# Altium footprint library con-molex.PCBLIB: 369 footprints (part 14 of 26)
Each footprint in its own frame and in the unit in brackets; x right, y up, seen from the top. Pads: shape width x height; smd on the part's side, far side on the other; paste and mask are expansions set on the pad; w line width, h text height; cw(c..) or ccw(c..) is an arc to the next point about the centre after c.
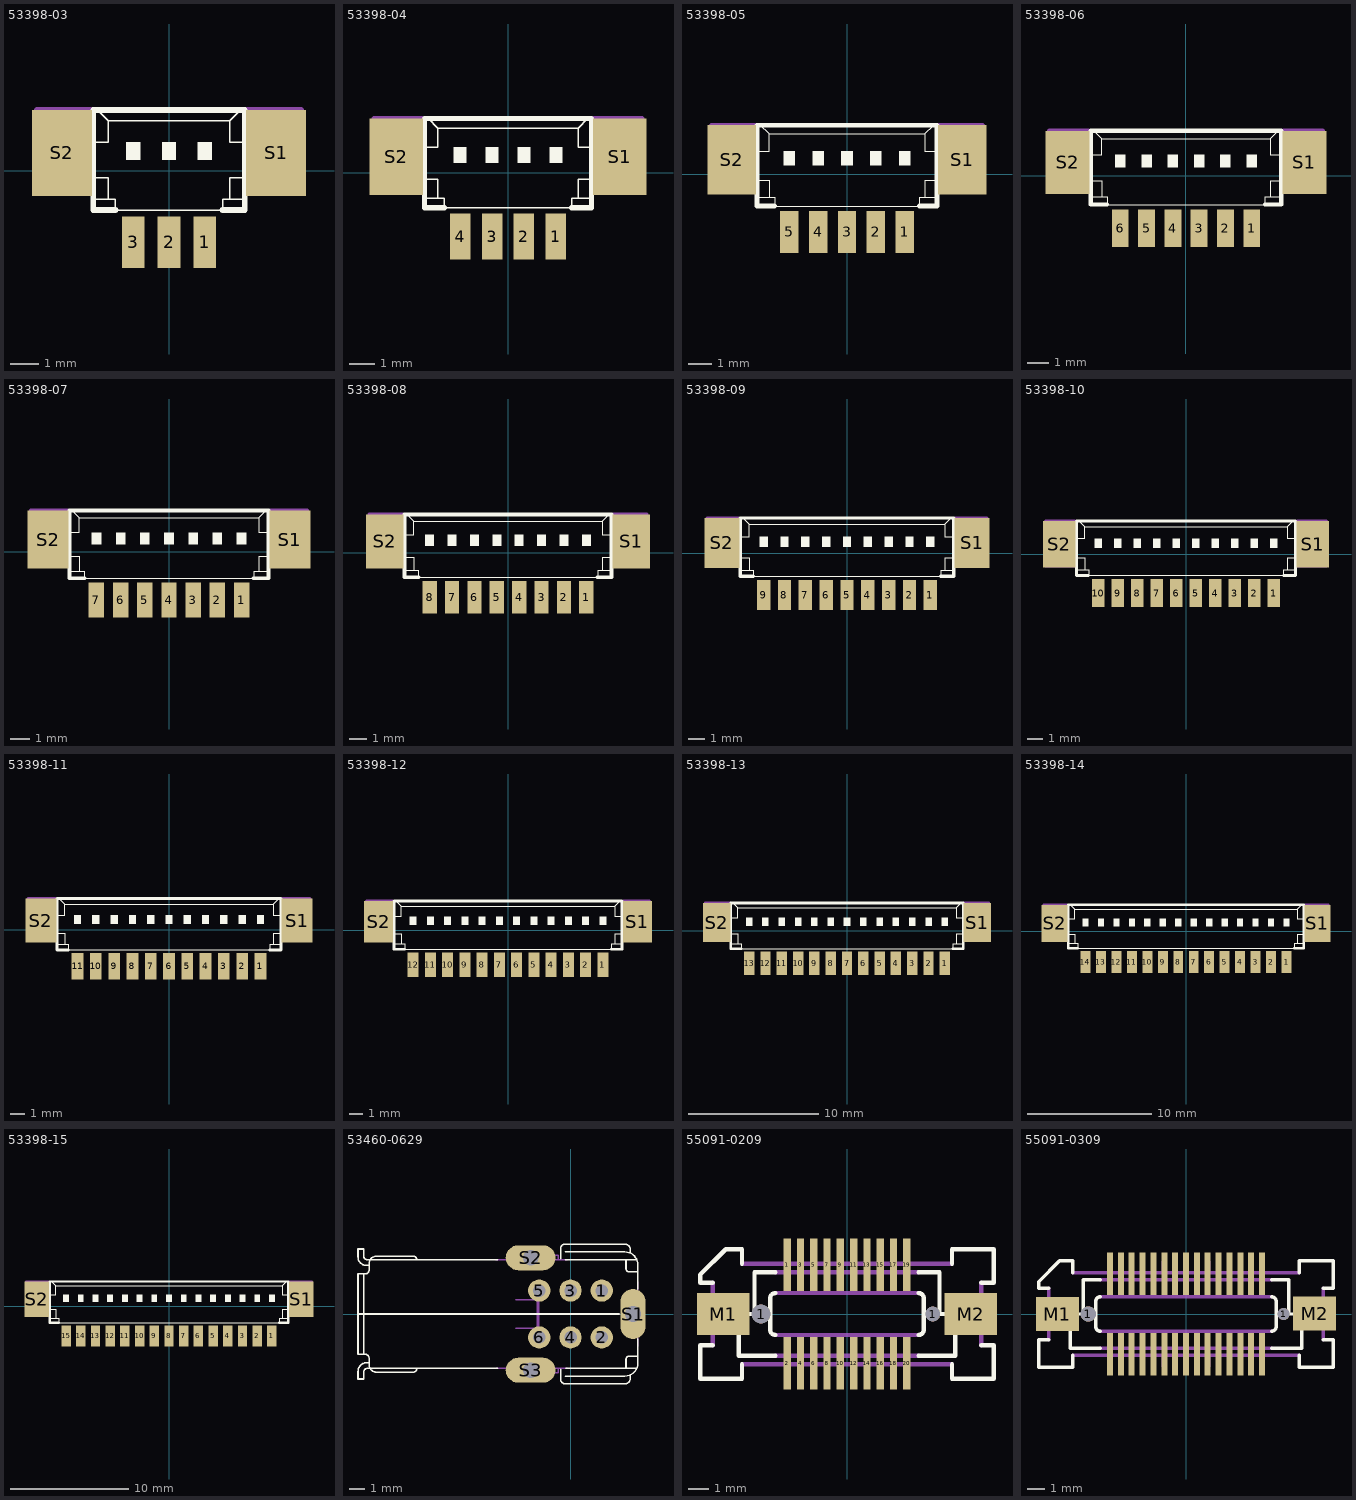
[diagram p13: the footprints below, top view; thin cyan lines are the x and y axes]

## 53398-03 [mil]
pads (5):
  rect 31.5x70.87 smd: 1(49.21,-98.43) 2(0,-98.43) 3(-49.21,-98.43)
  rect 82.68x118.11 smd: S1(147.64,24.61) S2(-147.64,24.61)
Top Overlay:
  rectangle: -59.06,14.76 -39.37,39.37
  rectangle: -9.84,14.76 9.84,39.37
  rectangle: 39.37,14.76 59.06,39.37
  lines w2: -103.35,-39.37 -83.66,-39.37 ; -103.35,-9.84 -83.66,-9.84 -83.66,-39.37 ; -103.35,39.37 -83.66,39.37 -83.66,68.9 ; -98.43,83.66 -83.66,68.9 ; 98.43,83.66 83.66,68.9 ; 103.35,-39.37 83.66,-39.37 ; 103.35,-9.84 83.66,-9.84 83.66,-39.37 ; 103.35,39.37 83.66,39.37 83.66,68.9 ; -83.66,-39.37 -73.82,-39.37 -73.82,-54.13 73.82,-54.13 73.82,-39.37 83.66,-39.37 ; -83.66,68.9 83.66,68.9
  lines w8: -73.82,-54.13 -104.33,-54.13 -104.33,83.66 -98.43,83.66 98.43,83.66 104.33,83.66 104.33,-54.13 73.82,-54.13
Mechanical 16:
  lines w8: -108.27,-29.53 -182.09,-29.53 -182.09,83.66 -108.27,83.66 ; 108.27,-29.53 182.09,-29.53 182.09,83.66 108.27,83.66
  text "1" at 123.03,-9.84 h117.8

## 53398-04 [mil]
pads (6):
  rect 31.5x70.87 smd: 1(73.82,-98.43) 2(24.61,-98.43) 3(-24.61,-98.43) 4(-73.82,-98.43)
  rect 82.68x118.11 smd: S1(172.24,24.61) S2(-172.24,24.61)
Top Overlay:
  rectangle: -83.66,14.76 -63.98,39.37
  rectangle: -34.45,14.76 -14.76,39.37
  rectangle: 14.76,14.76 34.45,39.37
  rectangle: 63.98,14.76 83.66,39.37
  lines w2: -127.95,-39.37 -108.27,-39.37 ; -127.95,-9.84 -108.27,-9.84 -108.27,-39.37 ; -127.95,39.37 -108.27,39.37 -108.27,68.9 ; -123.03,83.66 -108.27,68.9 ; 123.03,83.66 108.27,68.9 ; 127.95,-39.37 108.27,-39.37 ; 127.95,-9.84 108.27,-9.84 108.27,-39.37 ; 127.95,39.37 108.27,39.37 108.27,68.9 ; -108.27,-39.37 -98.43,-39.37 -98.43,-54.13 98.43,-54.13 98.43,-39.37 108.27,-39.37 ; -108.27,68.9 108.27,68.9
  lines w8: -98.43,-54.13 -128.94,-54.13 -128.94,83.66 -123.03,83.66 123.03,83.66 128.94,83.66 128.94,-54.13 98.43,-54.13
Mechanical 16:
  lines w8: -132.87,-29.53 -206.69,-29.53 -206.69,83.66 -132.87,83.66 ; 132.87,-29.53 206.69,-29.53 206.69,83.66 132.87,83.66
  text "1" at 147.64,-9.84 h117.8

## 53398-05 [mil]
pads (7):
  rect 31.5x70.87 smd: 1(98.43,-98.43) 2(49.21,-98.43) 3(0,-98.43) 4(-49.21,-98.43) 5(-98.43,-98.43)
  rect 82.68x118.11 smd: S1(196.85,24.61) S2(-196.85,24.61)
Top Overlay:
  rectangle: -108.27,14.76 -88.58,39.37
  rectangle: -59.06,14.76 -39.37,39.37
  rectangle: -9.84,14.76 9.84,39.37
  rectangle: 39.37,14.76 59.06,39.37
  rectangle: 88.58,14.76 108.27,39.37
  lines w2: -152.56,-39.37 -132.87,-39.37 ; -152.56,-9.84 -132.87,-9.84 -132.87,-39.37 ; -152.56,39.37 -132.87,39.37 -132.87,68.9 ; -147.64,83.66 -132.87,68.9 ; 147.64,83.66 132.87,68.9 ; 152.56,-39.37 132.87,-39.37 ; 152.56,-9.84 132.87,-9.84 132.87,-39.37 ; 152.56,39.37 132.87,39.37 132.87,68.9 ; -132.87,-39.37 -123.03,-39.37 -123.03,-54.13 123.03,-54.13 123.03,-39.37 132.87,-39.37 ; -132.87,68.9 132.87,68.9
  lines w8: -123.03,-54.13 -153.54,-54.13 -153.54,83.66 -147.64,83.66 147.64,83.66 153.54,83.66 153.54,-54.13 123.03,-54.13
Mechanical 16:
  lines w8: -157.48,-29.53 -231.3,-29.53 -231.3,83.66 -157.48,83.66 ; 157.48,-29.53 231.3,-29.53 231.3,83.66 157.48,83.66
  text "1" at 172.24,-9.84 h117.8

## 53398-06 [mil]
pads (8):
  rect 31.5x70.87 smd: 1(123.03,-98.43) 2(73.82,-98.43) 3(24.61,-98.43) 4(-24.61,-98.43) 5(-73.82,-98.43) 6(-123.03,-98.43)
  rect 82.68x118.11 smd: S1(221.46,24.61) S2(-221.46,24.61)
Top Overlay:
  rectangle: -132.87,14.76 -113.19,39.37
  rectangle: -83.66,14.76 -63.98,39.37
  rectangle: -34.45,14.76 -14.76,39.37
  rectangle: 14.76,14.76 34.45,39.37
  rectangle: 63.98,14.76 83.66,39.37
  rectangle: 113.19,14.76 132.87,39.37
  lines w2: -177.17,-39.37 -157.48,-39.37 ; -177.17,-9.84 -157.48,-9.84 -157.48,-39.37 ; -177.17,39.37 -157.48,39.37 -157.48,68.9 ; -172.24,83.66 -157.48,68.9 ; 172.24,83.66 157.48,68.9 ; 177.17,-39.37 157.48,-39.37 ; 177.17,-9.84 157.48,-9.84 157.48,-39.37 ; 177.17,39.37 157.48,39.37 157.48,68.9 ; -157.48,-39.37 -147.64,-39.37 -147.64,-54.13 147.64,-54.13 147.64,-39.37 157.48,-39.37 ; -157.48,68.9 157.48,68.9
  lines w8: -147.64,-54.13 -178.15,-54.13 -178.15,83.66 -172.24,83.66 172.24,83.66 178.15,83.66 178.15,-54.13 147.64,-54.13
Mechanical 16:
  lines w8: -182.09,-29.53 -255.91,-29.53 -255.91,83.66 -182.09,83.66 ; 182.09,-29.53 255.91,-29.53 255.91,83.66 182.09,83.66
  text "1" at 196.85,-9.84 h117.8

## 53398-07 [mil]
pads (9):
  rect 31.5x70.87 smd: 1(147.64,-98.43) 2(98.43,-98.43) 3(49.21,-98.43) 4(0,-98.43) 5(-49.21,-98.43) 6(-98.43,-98.43) 7(-147.64,-98.43)
  rect 82.68x118.11 smd: S1(246.06,24.61) S2(-246.06,24.61)
Top Overlay:
  rectangle: -157.48,14.76 -137.8,39.37
  rectangle: -108.27,14.76 -88.58,39.37
  rectangle: -59.06,14.76 -39.37,39.37
  rectangle: -9.84,14.76 9.84,39.37
  rectangle: 39.37,14.76 59.06,39.37
  rectangle: 88.58,14.76 108.27,39.37
  rectangle: 137.8,14.76 157.48,39.37
  lines w2: -201.77,-39.37 -182.09,-39.37 ; -201.77,-9.84 -182.09,-9.84 -182.09,-39.37 ; -201.77,39.37 -182.09,39.37 -182.09,68.9 ; -196.85,83.66 -182.09,68.9 ; 196.85,83.66 182.09,68.9 ; 201.77,-39.37 182.09,-39.37 ; 201.77,-9.84 182.09,-9.84 182.09,-39.37 ; 201.77,39.37 182.09,39.37 182.09,68.9 ; -182.09,-39.37 -172.24,-39.37 -172.24,-54.13 172.24,-54.13 172.24,-39.37 182.09,-39.37 ; -182.09,68.9 182.09,68.9
  lines w8: -172.24,-54.13 -202.76,-54.13 -202.76,83.66 -196.85,83.66 196.85,83.66 202.76,83.66 202.76,-54.13 172.24,-54.13
Mechanical 16:
  lines w8: -206.69,-29.53 -280.51,-29.53 -280.51,83.66 -206.69,83.66 ; 206.69,-29.53 280.51,-29.53 280.51,83.66 206.69,83.66
  text "1" at 221.46,-9.84 h117.8

## 53398-08 [mil]
pads (10):
  rect 31.5x70.87 smd: 1(172.24,-98.43) 2(123.03,-98.43) 3(73.82,-98.43) 4(24.61,-98.43) 5(-24.61,-98.43) 6(-73.82,-98.43) 7(-123.03,-98.43) 8(-172.24,-98.43)
  rect 82.68x118.11 smd: S1(270.67,24.61) S2(-270.67,24.61)
Top Overlay:
  rectangle: -182.09,14.76 -162.4,39.37
  rectangle: -132.87,14.76 -113.19,39.37
  rectangle: -83.66,14.76 -63.98,39.37
  rectangle: -34.45,14.76 -14.76,39.37
  rectangle: 14.76,14.76 34.45,39.37
  rectangle: 63.98,14.76 83.66,39.37
  rectangle: 113.19,14.76 132.87,39.37
  rectangle: 162.4,14.76 182.09,39.37
  lines w2: -226.38,-39.37 -206.69,-39.37 ; -226.38,-9.84 -206.69,-9.84 -206.69,-39.37 ; -226.38,39.37 -206.69,39.37 -206.69,68.9 ; -221.46,83.66 -206.69,68.9 ; 221.46,83.66 206.69,68.9 ; 226.38,-39.37 206.69,-39.37 ; 226.38,-9.84 206.69,-9.84 206.69,-39.37 ; 226.38,39.37 206.69,39.37 206.69,68.9 ; -206.69,-39.37 -196.85,-39.37 -196.85,-54.13 196.85,-54.13 196.85,-39.37 206.69,-39.37 ; -206.69,68.9 206.69,68.9
  lines w8: -196.85,-54.13 -227.36,-54.13 -227.36,83.66 -221.46,83.66 221.46,83.66 227.36,83.66 227.36,-54.13 196.85,-54.13
Mechanical 16:
  lines w8: -231.3,-29.53 -305.12,-29.53 -305.12,83.66 -231.3,83.66 ; 231.3,-29.53 305.12,-29.53 305.12,83.66 231.3,83.66
  text "1" at 246.06,-9.84 h117.8

## 53398-09 [mil]
pads (11):
  rect 31.5x70.87 smd: 1(196.85,-98.43) 2(147.64,-98.43) 3(98.43,-98.43) 4(49.21,-98.43) 5(0,-98.43) 6(-49.21,-98.43) 7(-98.43,-98.43) 8(-147.64,-98.43) 9(-196.85,-98.43)
  rect 82.68x118.11 smd: S1(295.28,24.61) S2(-295.28,24.61)
Top Overlay:
  rectangle: -206.69,14.76 -187.01,39.37
  rectangle: -157.48,14.76 -137.8,39.37
  rectangle: -108.27,14.76 -88.58,39.37
  rectangle: -59.06,14.76 -39.37,39.37
  rectangle: -9.84,14.76 9.84,39.37
  rectangle: 39.37,14.76 59.06,39.37
  rectangle: 88.58,14.76 108.27,39.37
  rectangle: 137.8,14.76 157.48,39.37
  rectangle: 187.01,14.76 206.69,39.37
  lines w2: -250.98,-39.37 -231.3,-39.37 ; -250.98,-9.84 -231.3,-9.84 -231.3,-39.37 ; -250.98,39.37 -231.3,39.37 -231.3,68.9 ; -246.06,83.66 -231.3,68.9 ; 246.06,83.66 231.3,68.9 ; 250.98,-39.37 231.3,-39.37 ; 250.98,-9.84 231.3,-9.84 231.3,-39.37 ; 250.98,39.37 231.3,39.37 231.3,68.9 ; -231.3,-39.37 -221.46,-39.37 -221.46,-54.13 221.46,-54.13 221.46,-39.37 231.3,-39.37 ; -231.3,68.9 231.3,68.9
  lines w8: -221.46,-54.13 -251.97,-54.13 -251.97,83.66 -246.06,83.66 246.06,83.66 251.97,83.66 251.97,-54.13 221.46,-54.13
Mechanical 16:
  lines w8: -255.91,-29.53 -329.72,-29.53 -329.72,83.66 -255.91,83.66 ; 255.91,-29.53 329.72,-29.53 329.72,83.66 255.91,83.66
  text "1" at 270.67,-9.84 h117.8

## 53398-10 [mil]
pads (12):
  rect 31.5x70.87 smd: 1(221.46,-98.43) 2(172.24,-98.43) 3(123.03,-98.43) 4(73.82,-98.43) 5(24.61,-98.43) 6(-24.61,-98.43) 7(-73.82,-98.43) 8(-123.03,-98.43) 9(-172.24,-98.43) 10(-221.46,-98.43)
  rect 82.68x118.11 smd: S1(319.88,24.61) S2(-319.88,24.61)
Top Overlay:
  rectangle: -231.3,14.76 -211.61,39.37
  rectangle: -182.09,14.76 -162.4,39.37
  rectangle: -132.87,14.76 -113.19,39.37
  rectangle: -83.66,14.76 -63.98,39.37
  rectangle: -34.45,14.76 -14.76,39.37
  rectangle: 14.76,14.76 34.45,39.37
  rectangle: 63.98,14.76 83.66,39.37
  rectangle: 113.19,14.76 132.87,39.37
  rectangle: 162.4,14.76 182.09,39.37
  rectangle: 211.61,14.76 231.3,39.37
  lines w2: -275.59,-39.37 -255.91,-39.37 ; -275.59,-9.84 -255.91,-9.84 -255.91,-39.37 ; -275.59,39.37 -255.91,39.37 -255.91,68.9 ; -270.67,83.66 -255.91,68.9 ; 270.67,83.66 255.91,68.9 ; 275.59,-39.37 255.91,-39.37 ; 275.59,-9.84 255.91,-9.84 255.91,-39.37 ; 275.59,39.37 255.91,39.37 255.91,68.9 ; -255.91,-39.37 -246.06,-39.37 -246.06,-54.13 246.06,-54.13 246.06,-39.37 255.91,-39.37 ; -255.91,68.9 255.91,68.9
  lines w8: -246.06,-54.13 -276.57,-54.13 -276.57,83.66 -270.67,83.66 270.67,83.66 276.57,83.66 276.57,-54.13 246.06,-54.13
Mechanical 16:
  lines w8: -280.51,-29.53 -354.33,-29.53 -354.33,83.66 -280.51,83.66 ; 280.51,-29.53 354.33,-29.53 354.33,83.66 280.51,83.66
  text "1" at 295.28,-9.84 h117.8

## 53398-11 [mil]
pads (13):
  rect 31.5x70.87 smd: 1(246.06,-98.43) 2(196.85,-98.43) 3(147.64,-98.43) 4(98.43,-98.43) 5(49.21,-98.43) 6(0,-98.43) 7(-49.21,-98.43) 8(-98.43,-98.43) 9(-147.64,-98.43) 10(-196.85,-98.43) 11(-246.06,-98.43)
  rect 82.68x118.11 smd: S1(344.49,24.61) S2(-344.49,24.61)
Top Overlay:
  rectangle: -255.91,14.76 -236.22,39.37
  rectangle: -206.69,14.76 -187.01,39.37
  rectangle: -157.48,14.76 -137.8,39.37
  rectangle: -108.27,14.76 -88.58,39.37
  rectangle: -59.06,14.76 -39.37,39.37
  rectangle: -9.84,14.76 9.84,39.37
  rectangle: 39.37,14.76 59.06,39.37
  rectangle: 88.58,14.76 108.27,39.37
  rectangle: 137.8,14.76 157.48,39.37
  rectangle: 187.01,14.76 206.69,39.37
  rectangle: 236.22,14.76 255.91,39.37
  lines w2: -300.2,-39.37 -280.51,-39.37 ; -300.2,-9.84 -280.51,-9.84 -280.51,-39.37 ; -300.2,39.37 -280.51,39.37 -280.51,68.9 ; -295.28,83.66 -280.51,68.9 ; 295.28,83.66 280.51,68.9 ; 300.2,-39.37 280.51,-39.37 ; 300.2,-9.84 280.51,-9.84 280.51,-39.37 ; 300.2,39.37 280.51,39.37 280.51,68.9 ; -280.51,-39.37 -270.67,-39.37 -270.67,-54.13 270.67,-54.13 270.67,-39.37 280.51,-39.37 ; -280.51,68.9 280.51,68.9
  lines w8: -270.67,-54.13 -301.18,-54.13 -301.18,83.66 -295.28,83.66 295.28,83.66 301.18,83.66 301.18,-54.13 270.67,-54.13
Mechanical 16:
  lines w8: -305.12,-29.53 -378.94,-29.53 -378.94,83.66 -305.12,83.66 ; 305.12,-29.53 378.94,-29.53 378.94,83.66 305.12,83.66
  text "1" at 319.88,-9.84 h117.8

## 53398-12 [mil]
pads (14):
  rect 31.5x70.87 smd: 1(270.67,-98.43) 2(221.46,-98.43) 3(172.24,-98.43) 4(123.03,-98.43) 5(73.82,-98.43) 6(24.61,-98.43) 7(-24.61,-98.43) 8(-73.82,-98.43) 9(-123.03,-98.43) 10(-172.24,-98.43) 11(-221.46,-98.43) 12(-270.67,-98.43)
  rect 82.68x118.11 smd: S1(369.09,24.61) S2(-369.09,24.61)
Top Overlay:
  rectangle: -280.51,14.76 -260.83,39.37
  rectangle: -231.3,14.76 -211.61,39.37
  rectangle: -182.09,14.76 -162.4,39.37
  rectangle: -132.87,14.76 -113.19,39.37
  rectangle: -83.66,14.76 -63.98,39.37
  rectangle: -34.45,14.76 -14.76,39.37
  rectangle: 14.76,14.76 34.45,39.37
  rectangle: 63.98,14.76 83.66,39.37
  rectangle: 113.19,14.76 132.87,39.37
  rectangle: 162.4,14.76 182.09,39.37
  rectangle: 211.61,14.76 231.3,39.37
  rectangle: 260.83,14.76 280.51,39.37
  lines w2: -324.8,-39.37 -305.12,-39.37 ; -324.8,-9.84 -305.12,-9.84 -305.12,-39.37 ; -324.8,39.37 -305.12,39.37 -305.12,68.9 ; -319.88,83.66 -305.12,68.9 ; 319.88,83.66 305.12,68.9 ; 324.8,-39.37 305.12,-39.37 ; 324.8,-9.84 305.12,-9.84 305.12,-39.37 ; 324.8,39.37 305.12,39.37 305.12,68.9 ; -305.12,-39.37 -295.28,-39.37 -295.28,-54.13 295.28,-54.13 295.28,-39.37 305.12,-39.37 ; -305.12,68.9 305.12,68.9
  lines w8: -295.28,-54.13 -325.79,-54.13 -325.79,83.66 -319.88,83.66 319.88,83.66 325.79,83.66 325.79,-54.13 295.28,-54.13
Mechanical 16:
  lines w8: -329.72,-29.53 -403.54,-29.53 -403.54,83.66 -329.72,83.66 ; 329.72,-29.53 403.54,-29.53 403.54,83.66 329.72,83.66
  text "1" at 344.49,-9.84 h117.8

## 53398-13 [mil]
pads (15):
  rect 31.5x70.87 smd: 1(295.28,-98.43) 2(246.06,-98.43) 3(196.85,-98.43) 4(147.64,-98.43) 5(98.43,-98.43) 6(49.21,-98.43) 7(0,-98.43) 8(-49.21,-98.43) 9(-98.43,-98.43) 10(-147.64,-98.43) 11(-196.85,-98.43) 12(-246.06,-98.43) 13(-295.28,-98.43)
  rect 82.68x118.11 smd: S1(393.7,24.61) S2(-393.7,24.61)
Top Overlay:
  rectangle: -305.12,14.76 -285.43,39.37
  rectangle: -255.91,14.76 -236.22,39.37
  rectangle: -206.69,14.76 -187.01,39.37
  rectangle: -157.48,14.76 -137.8,39.37
  rectangle: -108.27,14.76 -88.58,39.37
  rectangle: -59.06,14.76 -39.37,39.37
  rectangle: -9.84,14.76 9.84,39.37
  rectangle: 39.37,14.76 59.06,39.37
  rectangle: 88.58,14.76 108.27,39.37
  rectangle: 137.8,14.76 157.48,39.37
  rectangle: 187.01,14.76 206.69,39.37
  rectangle: 236.22,14.76 255.91,39.37
  rectangle: 285.43,14.76 305.12,39.37
  lines w2: -349.41,-39.37 -329.72,-39.37 ; -349.41,-9.84 -329.72,-9.84 -329.72,-39.37 ; -349.41,39.37 -329.72,39.37 -329.72,68.9 ; -344.49,83.66 -329.72,68.9 ; 344.49,83.66 329.72,68.9 ; 349.41,-39.37 329.72,-39.37 ; 349.41,-9.84 329.72,-9.84 329.72,-39.37 ; 349.41,39.37 329.72,39.37 329.72,68.9 ; -329.72,-39.37 -319.88,-39.37 -319.88,-54.13 319.88,-54.13 319.88,-39.37 329.72,-39.37 ; -329.72,68.9 329.72,68.9
  lines w8: -319.88,-54.13 -350.39,-54.13 -350.39,83.66 -344.49,83.66 344.49,83.66 350.39,83.66 350.39,-54.13 319.88,-54.13
Mechanical 16:
  lines w8: -354.33,-29.53 -428.15,-29.53 -428.15,83.66 -354.33,83.66 ; 354.33,-29.53 428.15,-29.53 428.15,83.66 354.33,83.66
  text "1" at 369.09,-9.84 h117.8

## 53398-14 [mil]
pads (16):
  rect 31.5x70.87 smd: 1(319.88,-98.43) 2(270.67,-98.43) 3(221.46,-98.43) 4(172.24,-98.43) 5(123.03,-98.43) 6(73.82,-98.43) 7(24.61,-98.43) 8(-24.61,-98.43) 9(-73.82,-98.43) 10(-123.03,-98.43) 11(-172.24,-98.43) 12(-221.46,-98.43) 13(-270.67,-98.43) 14(-319.88,-98.43)
  rect 82.68x118.11 smd: S1(418.31,24.61) S2(-418.31,24.61)
Top Overlay:
  rectangle: -329.72,14.76 -310.04,39.37
  rectangle: -280.51,14.76 -260.83,39.37
  rectangle: -231.3,14.76 -211.61,39.37
  rectangle: -182.09,14.76 -162.4,39.37
  rectangle: -132.87,14.76 -113.19,39.37
  rectangle: -83.66,14.76 -63.98,39.37
  rectangle: -34.45,14.76 -14.76,39.37
  rectangle: 14.76,14.76 34.45,39.37
  rectangle: 63.98,14.76 83.66,39.37
  rectangle: 113.19,14.76 132.87,39.37
  rectangle: 162.4,14.76 182.09,39.37
  rectangle: 211.61,14.76 231.3,39.37
  rectangle: 260.83,14.76 280.51,39.37
  rectangle: 310.04,14.76 329.72,39.37
  lines w2: -374.02,-39.37 -354.33,-39.37 ; -374.02,-9.84 -354.33,-9.84 -354.33,-39.37 ; -374.02,39.37 -354.33,39.37 -354.33,68.9 ; -369.09,83.66 -354.33,68.9 ; 369.09,83.66 354.33,68.9 ; 374.02,-39.37 354.33,-39.37 ; 374.02,-9.84 354.33,-9.84 354.33,-39.37 ; 374.02,39.37 354.33,39.37 354.33,68.9 ; -354.33,-39.37 -344.49,-39.37 -344.49,-54.13 344.49,-54.13 344.49,-39.37 354.33,-39.37 ; -354.33,68.9 354.33,68.9
  lines w8: -344.49,-54.13 -375,-54.13 -375,83.66 -369.09,83.66 369.09,83.66 375,83.66 375,-54.13 344.49,-54.13
Mechanical 16:
  lines w8: -378.94,-29.53 -452.76,-29.53 -452.76,83.66 -378.94,83.66 ; 378.94,-29.53 452.76,-29.53 452.76,83.66 378.94,83.66
  text "1" at 393.7,-9.84 h117.8

## 53398-15 [mil]
pads (17):
  rect 31.5x70.87 smd: 1(344.49,-98.43) 2(295.28,-98.43) 3(246.06,-98.43) 4(196.85,-98.43) 5(147.64,-98.43) 6(98.43,-98.43) 7(49.21,-98.43) 8(0,-98.43) 9(-49.21,-98.43) 10(-98.43,-98.43) 11(-147.64,-98.43) 12(-196.85,-98.43) 13(-246.06,-98.43) 14(-295.28,-98.43) 15(-344.49,-98.43)
  rect 82.68x118.11 smd: S1(442.91,24.61) S2(-442.91,24.61)
Top Overlay:
  rectangle: -354.33,14.76 -334.65,39.37
  rectangle: -305.12,14.76 -285.43,39.37
  rectangle: -255.91,14.76 -236.22,39.37
  rectangle: -206.69,14.76 -187.01,39.37
  rectangle: -157.48,14.76 -137.8,39.37
  rectangle: -108.27,14.76 -88.58,39.37
  rectangle: -59.06,14.76 -39.37,39.37
  rectangle: -9.84,14.76 9.84,39.37
  rectangle: 39.37,14.76 59.06,39.37
  rectangle: 88.58,14.76 108.27,39.37
  rectangle: 137.8,14.76 157.48,39.37
  rectangle: 187.01,14.76 206.69,39.37
  rectangle: 236.22,14.76 255.91,39.37
  rectangle: 285.43,14.76 305.12,39.37
  rectangle: 334.65,14.76 354.33,39.37
  lines w2: -398.62,-39.37 -378.94,-39.37 ; -398.62,-9.84 -378.94,-9.84 -378.94,-39.37 ; -398.62,39.37 -378.94,39.37 -378.94,68.9 ; -393.7,83.66 -378.94,68.9 ; 393.7,83.66 378.94,68.9 ; 398.62,-39.37 378.94,-39.37 ; 398.62,-9.84 378.94,-9.84 378.94,-39.37 ; 398.62,39.37 378.94,39.37 378.94,68.9 ; -378.94,-39.37 -369.09,-39.37 -369.09,-54.13 369.09,-54.13 369.09,-39.37 378.94,-39.37 ; -378.94,68.9 378.94,68.9
  lines w8: -369.09,-54.13 -378.94,-54.13 -399.61,-54.13 -399.61,83.66 -393.7,83.66 393.7,83.66 399.61,83.66 399.61,-54.13 378.94,-54.13 369.09,-54.13
Mechanical 16:
  lines w8: -403.54,-29.53 -477.36,-29.53 -477.36,83.66 -403.54,83.66 ; 403.54,-29.53 477.36,-29.53 477.36,83.66 403.54,83.66
  text "1" at 418.31,-9.84 h117.8

## 53460-0629 [mil]
pads (9):
  round 56 hole 31.5: 1(78.74,59.06) 2(78.74,-59.06) 3(0,59.06) 4(0,-59.06) 5(-78.74,59.06) 6(-78.74,-59.06)
  oval 62.99x125.98 hole 39.37: S1(157.48,0)
  oval 125.98x62.99 hole 39.37: S2(-100.39,141.73) S3(-100.39,-141.73)
Top Overlay:
  lines w4: -532.83,0 122.35,0 ; -520.8,-100.28 -520.8,99.61 ; -509.43,-122.34 -512.77,-122.34 ccw(c-512.77,-145.07) -535.5,-145.07 -535.5,-163.79 -520.8,-163.79 -520.8,-145.74 cw(c-512.11,-145.75) -512.1,-137.05 -183.53,-137.05 ; -508.76,122.35 -514.11,122.35 cw(c-514.11,143.74) -535.5,143.74 -535.5,163.8 -520.8,163.8 -520.8,145.08 ccw(c-512.77,145.09) -512.77,137.06 -183.53,137.06 ; -507.43,110.98 cw(c-517.45,110.97) -517.45,100.95 -535.5,100.96 -535.5,-101.62 -517.45,-101.62 cw(c-517.45,-111.65) -507.42,-111.65 -507.42,-128.36 ccw(c-489.37,-128.36) -489.37,-146.41 -395.78,-146.41 ccw(c-395.77,-138.38) -387.75,-138.39 ; -507.42,110.98 -507.42,127.69 ; -387.76,137.72 ccw(c-395.78,137.72) -395.78,145.74 -489.37,145.74 ccw(c-489.37,127.69) -507.42,127.69 ; -24.74,-139.06 -24.74,-165.13 ccw(c-14.03,-165.13) -14.04,-175.83 137.72,-175.83 ; -24.74,139.06 -24.74,165.13 cw(c-14.04,165.13) -14.04,175.83 137.72,175.83 cw(c137.72,163.12) 150.43,163.13 150.43,155.77 ; -13.37,-156.44 137.05,-156.44 ccw(c137.05,-123.68) 169.81,-123.68 169.81,-106.3 ; -13.37,156.44 137.05,156.44 cw(c137.05,123.68) 169.81,123.68 169.81,106.3 ; -12.77,137.06 166.47,137.06 ; -12.1,-137.05 166.47,-137.05 ; 139.72,-114.32 cw(c147.75,-114.33) 147.75,-106.3 169.81,-106.3 ; 139.73,-135.04 139.73,-114.32 ; 139.73,135.05 139.73,114.32 ccw(c147.75,114.32) 147.75,106.3 169.81,106.3 ; 150.42,-163.13 cw(c137.72,-163.13) 137.72,-175.83 ; 150.43,-163.13 150.43,-155.77 ; 169.81,-62.44 169.81,-106.3 ; 169.81,62.44 169.81,106.3 ; -507.42,127.69 -507.42,127.69 ; 137.72,-175.83 137.72,-175.83 ; 169.81,0 169.81,0
Mechanical 11:
  lines w0: -139.76,-141.73 cw(c-120.08,-141.73) -120.08,-122.05 -80.71,-122.05 cw(c-80.7,-141.74) -61.02,-141.73 cw(c-80.71,-141.73) -80.71,-161.42 -120.08,-161.42 cw(c-120.08,-141.74) -139.76,-141.73 ; -139.76,141.73 cw(c-120.08,141.74) -120.08,161.42 -80.71,161.42 cw(c-80.71,141.73) -61.02,141.73 cw(c-80.7,141.74) -80.71,122.05 -120.08,122.05 cw(c-120.08,141.73) -139.76,141.73 ; 137.8,-19.69 ccw(c157.48,-19.69) 157.48,-39.37 ccw(c157.49,-19.68) 177.17,-19.69 177.17,19.69 ccw(c157.49,19.68) 157.48,39.37 ccw(c157.48,19.69) 137.8,19.69 137.8,-19.69
Mechanical 16:
  lines w4: -187.77,137.06 -8.53,137.06 ; -187.1,-137.05 -8.53,-137.05 ; -143.07,-139.06 -143.07,-148.42 -124.35,-148.41 ccw(c-122.34,-148.41) -122.34,-150.42 -66.85,-150.42 ccw(c-66.86,-148.41) -64.85,-148.41 -30.75,-148.41 -30.75,-139.06 ; -143.07,139.06 -143.07,148.42 -124.35,148.42 cw(c-122.34,148.42) -122.34,150.43 -66.85,150.43 cw(c-66.86,148.43) -64.85,148.42 -30.75,148.42 -30.75,139.06 ; -137.72,-35.43 -80.22,-35.43 -80.22,35.43 -137.72,35.43 ; -84.24,-34.09 -84.24,33.43 ; 150.42,-37.44 150.42,-1.33 ; 150.43,-37.44 ccw(c159.12,-37.45) 159.11,-46.13 161.12,-46.13 ccw(c161.11,-37.43) 169.81,-37.44 ; 150.43,1.34 150.43,37.44 cw(c159.12,37.44) 159.11,46.13 161.12,46.13 cw(c161.12,37.44) 169.81,37.44 ; 169.81,-81.3 169.81,-37.44 ; 169.81,81.3 169.81,37.44 ; 169.81,-37.44 169.81,37.44

## 55091-0209 [mm]
pads (24):
  round 0.9 hole 0.9: 1(-4.11,0)
  rect 0.35x2.5 smd: 1(-2.857,2.35) 2(-2.857,-2.35) 3(-2.222,2.35) 4(-2.222,-2.35) 5(-1.587,2.35) 6(-1.587,-2.35) 7(-0.953,2.35) 8(-0.953,-2.35) 9(-0.318,2.35) 10(-0.318,-2.35) 11(0.318,2.35) 12(0.318,-2.35) 13(0.953,2.35) 14(0.953,-2.35) 15(1.587,2.35) 16(1.587,-2.35) 17(2.222,2.35) 18(2.222,-2.35) 19(2.857,2.35) 20(2.857,-2.35)
  round 0.7 hole 0.7: 1(4.11,0)
  rect 2.5x2 smd: M1(-5.925,0) M2(5.925,0)
Top Overlay:
  lines w0.203: -6.425,-1.5 -7.025,-1.5 -7.025,-3.1 -5.025,-3.1 -5.025,-2.4 ; -6.425,1.5 -7.025,1.5 -7.025,1.875 -5.8,3.1 -5.025,3.1 -5.025,2.4 ; -3.425,-2 -5.175,-2 -5.175,0 -4.425,0 -4.425,2 -3.425,2 ; -3.425,-1 cw(c-3.425,-0.75) -3.675,-0.75 -3.675,0.75 cw(c-3.425,0.75) -3.425,1 ; 3.425,-2 5.175,-2 5.175,0 4.425,0 4.425,2 3.425,2 ; 3.425,-1 ccw(c3.425,-0.75) 3.675,-0.75 3.675,0.75 ccw(c3.425,0.75) 3.425,1 ; 5.025,-2.4 5.025,-3.1 7.025,-3.1 7.025,-1.5 6.425,-1.5 ; 5.025,2.4 5.025,3.1 7.025,3.1 7.025,1.5 6.425,1.5
Top Solder:
  rectangle: -3.057,1.075 -2.658,3.625
  region: -2.658,-1.075 -3.057,-1.075 -3.057,-3.625 -2.658,-3.625
  rectangle: -2.422,1.075 -2.023,3.625
  region: -2.023,-1.075 -2.422,-1.075 -2.422,-3.625 -2.023,-3.625
  rectangle: -1.787,1.075 -1.388,3.625
  region: -1.388,-1.075 -1.787,-1.075 -1.787,-3.625 -1.388,-3.625
  rectangle: -1.152,1.075 -0.753,3.625
  region: -0.753,-1.075 -1.152,-1.075 -1.152,-3.625 -0.753,-3.625
  rectangle: -0.517,1.075 -0.118,3.625
  region: -0.118,-1.075 -0.517,-1.075 -0.517,-3.625 -0.118,-3.625
  rectangle: 0.118,1.075 0.517,3.625
  region: 0.517,-1.075 0.118,-1.075 0.118,-3.625 0.517,-3.625
  rectangle: 0.753,1.075 1.152,3.625
  region: 1.152,-1.075 0.753,-1.075 0.753,-3.625 1.152,-3.625
  rectangle: 1.388,1.075 1.787,3.625
  region: 1.787,-1.075 1.388,-1.075 1.388,-3.625 1.787,-3.625
  rectangle: 2.023,1.075 2.422,3.625
  region: 2.422,-1.075 2.023,-1.075 2.023,-3.625 2.422,-3.625
  rectangle: 2.658,1.075 3.057,3.625
  region: 3.057,-1.075 2.658,-1.075 2.658,-3.625 3.057,-3.625
Mechanical 16:
  rectangle: -3.008,-3.1 -2.707,-2.375
  region: -2.707,3.1 -3.008,3.1 -3.008,2.375 -2.707,2.375
  rectangle: -2.373,-3.1 -2.072,-2.375
  region: -2.072,3.1 -2.373,3.1 -2.373,2.375 -2.072,2.375
  rectangle: -1.738,-3.1 -1.437,-2.375
  region: -1.437,3.1 -1.738,3.1 -1.738,2.375 -1.437,2.375
  rectangle: -1.103,-3.1 -0.802,-2.375
  region: -0.802,3.1 -1.103,3.1 -1.103,2.375 -0.802,2.375
  rectangle: -0.468,-3.1 -0.167,-2.375
  region: -0.167,3.1 -0.468,3.1 -0.468,2.375 -0.167,2.375
  rectangle: 0.167,-3.1 0.468,-2.375
  region: 0.468,3.1 0.167,3.1 0.167,2.375 0.468,2.375
  rectangle: 0.802,-3.1 1.103,-2.375
  region: 1.103,3.1 0.802,3.1 0.802,2.375 1.103,2.375
  rectangle: 1.437,-3.1 1.738,-2.375
  region: 1.738,3.1 1.437,3.1 1.437,2.375 1.738,2.375
  rectangle: 2.072,-3.1 2.373,-2.375
  region: 2.373,3.1 2.072,3.1 2.072,2.375 2.373,2.375
  rectangle: 2.707,-3.1 3.008,-2.375
  region: 3.008,3.1 2.707,3.1 2.707,2.375 3.008,2.375
  lines w0.203: -6.425,-1.5 -6.425,1.5 ; -5.025,-2.4 5.025,-2.4 ; -5.025,2.4 5.025,2.4 ; -3.425,-2 3.425,-2 ; -3.425,-1 3.425,-1 ; -3.425,1 3.425,1 ; -3.425,2 3.425,2 ; 6.425,-1.5 6.425,1.5

## 55091-0309 [mm]
pads (34):
  round 0.9 hole 0.9: 1(-5.7,0)
  rect 0.35x2.5 smd: 1(-4.445,2.35) 2(-4.445,-2.35) 3(-3.81,2.35) 4(-3.81,-2.35) 5(-3.175,2.35) 6(-3.175,-2.35) 7(-2.54,2.35) 8(-2.54,-2.35) 9(-1.905,2.35) 10(-1.905,-2.35) 11(-1.27,2.35) 12(-1.27,-2.35) 13(-0.635,2.35) 14(-0.635,-2.35) 15(0,2.35) 16(0,-2.35) 17(0.635,2.35) 18(0.635,-2.35) 19(1.27,2.35) 20(1.27,-2.35) 21(1.905,2.35) 22(1.905,-2.35) 23(2.54,2.35) 24(2.54,-2.35) 25(3.175,2.35) 26(3.175,-2.35) 27(3.81,2.35) 28(3.81,-2.35) 29(4.445,2.35) 30(4.445,-2.35)
  round 0.7 hole 0.7: 1(5.7,0)
  rect 2.5x2 smd: M1(-7.513,0) M2(7.513,0.025)
Top Overlay:
  lines w0.203: -8.012,-1.5 -8.612,-1.5 -8.612,-3.1 -6.612,-3.1 -6.612,-2.4 ; -8.012,1.5 -8.612,1.5 -8.612,1.875 -7.388,3.1 -6.612,3.1 -6.612,2.4 ; -5.012,-2 -6.762,-2 -6.762,0 -6.012,0 -6.012,2 -5.012,2 ; -5.012,-1 cw(c-5.013,-0.75) -5.263,-0.75 -5.263,0.75 cw(c-5.013,0.75) -5.012,1 ; 5.012,-2 6.762,-2 6.762,0 6.012,0 6.012,2 5.012,2 ; 5.012,-1 ccw(c5.013,-0.75) 5.263,-0.75 5.263,0.75 ccw(c5.013,0.75) 5.012,1 ; 6.612,-2.4 6.612,-3.1 8.612,-3.1 8.612,-1.5 8.012,-1.5 ; 6.612,2.4 6.612,3.1 8.612,3.1 8.612,1.5 8.012,1.5
Top Solder:
  rectangle: -4.645,1.075 -4.245,3.625
  region: -4.245,-1.075 -4.645,-1.075 -4.645,-3.625 -4.245,-3.625
  rectangle: -4.01,1.075 -3.61,3.625
  region: -3.61,-1.075 -4.01,-1.075 -4.01,-3.625 -3.61,-3.625
  rectangle: -3.375,1.075 -2.975,3.625
  region: -2.975,-1.075 -3.375,-1.075 -3.375,-3.625 -2.975,-3.625
  rectangle: -2.74,1.075 -2.34,3.625
  region: -2.34,-1.075 -2.74,-1.075 -2.74,-3.625 -2.34,-3.625
  rectangle: -2.105,1.075 -1.705,3.625
  region: -1.705,-1.075 -2.105,-1.075 -2.105,-3.625 -1.705,-3.625
  rectangle: -1.47,1.075 -1.07,3.625
  region: -1.07,-1.075 -1.47,-1.075 -1.47,-3.625 -1.07,-3.625
  rectangle: -0.835,1.075 -0.435,3.625
  region: -0.435,-1.075 -0.835,-1.075 -0.835,-3.625 -0.435,-3.625
  rectangle: -0.2,1.075 0.2,3.625
  region: 0.2,-1.075 -0.2,-1.075 -0.2,-3.625 0.2,-3.625
  rectangle: 0.435,1.075 0.835,3.625
  region: 0.835,-1.075 0.435,-1.075 0.435,-3.625 0.835,-3.625
  rectangle: 1.07,1.075 1.47,3.625
  region: 1.47,-1.075 1.07,-1.075 1.07,-3.625 1.47,-3.625
  rectangle: 1.705,1.075 2.105,3.625
  region: 2.105,-1.075 1.705,-1.075 1.705,-3.625 2.105,-3.625
  rectangle: 2.34,1.075 2.74,3.625
  region: 2.74,-1.075 2.34,-1.075 2.34,-3.625 2.74,-3.625
  rectangle: 2.975,1.075 3.375,3.625
  region: 3.375,-1.075 2.975,-1.075 2.975,-3.625 3.375,-3.625
  rectangle: 3.61,1.075 4.01,3.625
  region: 4.01,-1.075 3.61,-1.075 3.61,-3.625 4.01,-3.625
  rectangle: 4.245,1.075 4.645,3.625
  region: 4.645,-1.075 4.245,-1.075 4.245,-3.625 4.645,-3.625
Mechanical 16:
  rectangle: -4.595,-3.1 -4.295,-2.375
  region: -4.295,3.1 -4.595,3.1 -4.595,2.375 -4.295,2.375
  rectangle: -3.96,-3.1 -3.66,-2.375
  region: -3.66,3.1 -3.96,3.1 -3.96,2.375 -3.66,2.375
  rectangle: -3.325,-3.1 -3.025,-2.375
  region: -3.025,3.1 -3.325,3.1 -3.325,2.375 -3.025,2.375
  rectangle: -2.69,-3.1 -2.39,-2.375
  region: -2.39,3.1 -2.69,3.1 -2.69,2.375 -2.39,2.375
  rectangle: -2.055,-3.1 -1.755,-2.375
  region: -1.755,3.1 -2.055,3.1 -2.055,2.375 -1.755,2.375
  rectangle: -1.42,-3.1 -1.12,-2.375
  region: -1.12,3.1 -1.42,3.1 -1.42,2.375 -1.12,2.375
  rectangle: -0.785,-3.1 -0.485,-2.375
  region: -0.485,3.1 -0.785,3.1 -0.785,2.375 -0.485,2.375
  rectangle: -0.15,-3.1 0.15,-2.375
  region: 0.15,3.1 -0.15,3.1 -0.15,2.375 0.15,2.375
  rectangle: 0.485,-3.1 0.785,-2.375
  region: 0.785,3.1 0.485,3.1 0.485,2.375 0.785,2.375
  rectangle: 1.12,-3.1 1.42,-2.375
  region: 1.42,3.1 1.12,3.1 1.12,2.375 1.42,2.375
  rectangle: 1.755,-3.1 2.055,-2.375
  region: 2.055,3.1 1.755,3.1 1.755,2.375 2.055,2.375
  rectangle: 2.39,-3.1 2.69,-2.375
  region: 2.69,3.1 2.39,3.1 2.39,2.375 2.69,2.375
  rectangle: 3.025,-3.1 3.325,-2.375
  region: 3.325,3.1 3.025,3.1 3.025,2.375 3.325,2.375
  rectangle: 3.66,-3.1 3.96,-2.375
  region: 3.96,3.1 3.66,3.1 3.66,2.375 3.96,2.375
  rectangle: 4.295,-3.1 4.595,-2.375
  region: 4.595,3.1 4.295,3.1 4.295,2.375 4.595,2.375
  lines w0.203: -8.012,-1.5 -8.012,1.5 ; -6.612,-2.4 6.612,-2.4 ; -6.612,2.4 6.612,2.4 ; -5.012,-2 5.012,-2 ; -5.012,-1 5.012,-1 ; -5.012,1 5.012,1 ; -5.012,2 5.012,2 ; 8.012,-1.5 8.012,1.5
